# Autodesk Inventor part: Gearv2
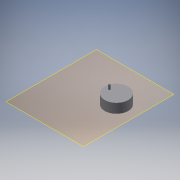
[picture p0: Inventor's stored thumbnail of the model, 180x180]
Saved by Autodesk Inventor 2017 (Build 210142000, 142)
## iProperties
Created: 2017-05
Part Number: Gearv2
Material: Generic
Document SubType Name: Modeling
Designer: 1717440
Density: 1 g/cm^3
Appearance: Default
Author: 1717440
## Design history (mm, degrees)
workplane "Work Plane4"
sketch "Sketch5"
  geometry: L1 (-28.282, 83.089)-(-22.969, 93.849); L2 (-22.837, 90.883)-(-24, 86); L3 (-25.404, 92.15)-(-28.574, 88.259); C1 r 3.386 at (-28.282, 83.089) reference; C2 r 2 at (-22.969, 93.849) reference; A1 r 5.178 centre (-28.282, 83.089) between (-28.574, 88.259) and (-24, 86); A2 r 2.969 centre (-22.969, 93.849) between (-22.837, 90.883) and (-25.404, 92.15); 3 further points
  constraints: 6 end point, 4 point on circle, 3 symmetric about line, 2 centre point, 2 coincident
extrude "Extrusion4" new body sketch "Sketch5" distance "d9" = 4.75; taper "d10" = 0 deg
sketch "Sketch6"
  geometry: C1 r 3.386 at (83.089, -28.282) reference; 1 further point
extrude "Extrusion5" join sketch "Sketch6" distance "d11" = 25; taper "d12" = 0 deg
sketch "Sketch7"
  geometry: L1 (-92.15, -25.404)-(-88.259, -28.574) reference; L2 (-86, -24)-(-90.883, -22.837) reference; C1 r 2 at (-93.849, -22.969) reference; C2 r 2.5 at (-93.849, -22.969); A1 r 5.178 centre (-83.089, -28.282) between (-88.259, -28.574) and (-86, -24) reference; A2 r 2.969 centre (-93.849, -22.969) between (-90.883, -22.837) and (-92.15, -25.404) reference; 1 further point
  constraints: 1 centre point, 1 coincident
  dimensions: "d13" = 5 diameter of C2
  node "Projected Loop1"
  node "Reference5"
workplane "Work Plane5"
extrude "Extrusion7" join sketch "Sketch7" stored distance "d16" = 5 (= d13); taper "d17" = 0 deg
sketch "Sketch8"
  geometry: C1 r 2 at (0, 0) reference; 1 further point
  node "Reference6"
workplane "Work Plane6"
extrude "Extrusion8" join sketch "Sketch8" stored distance "d18" = 5 (= d13); taper "d19" = 0 deg
sketch "Sketch9"
  geometry: L1 (-3.915, 0.5)-(0, 0.5); L2 (0, 0.5)-(0, 0); L3 (-3.915, -0.5)-(0, -0.5); L4 (0, -0.5)-(0, 0); L5 (-1.5, 0.5)-(-1.5, -0.5); L6 (-3.915, 0.5)-(-3.915, -0.5); C1 r 3.386 at (0, 0) reference; 1 further point
  constraints: 12 end point, 2 point on line, 1 perpendicular, 1 vertical
  dimensions: "d22" = 1.5 distance between parallel lines of L5 L2
workplane "Work Plane7"
extrude "Extrusion9" cut sketch "Sketch9" stored distance "d23" = 5 (= d13); taper "d24" = 0 deg
body "Solid2"
node "Reference2"
node "Reference3"
node "Reference4"
